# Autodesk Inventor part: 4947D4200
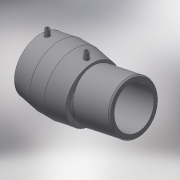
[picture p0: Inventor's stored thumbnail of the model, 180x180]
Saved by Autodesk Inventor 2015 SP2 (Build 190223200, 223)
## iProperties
Created: 2017-06
Part Number: 4947D4200
Material: Generic
Description: PLASSON ADJUSTABLE ELBOW (ONE SIDE) 200
Document SubType Name: Modeling
Designer: KIM
Mass: 55.0731 g
Surface Area: 148.067 cm^2
Volume: 55.0731 cm^3
Density: 1 g/cm^3
Appearance: Default
Author: KIM
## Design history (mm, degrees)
derived "4947D4.ipt"
feature "Solid1::4947D4.ipt"
tag "TaggingFeature1"
body "Solid1"
other parameters: "d0" = 194.25, "d3" = 104, "d4" = 52, "d5" = 225, "d8" = 168 deg, "d10" = 41.6, "d11" = 13.86667, "d29" = 125, "d30" = 15, "d31" = 74, "d34" = 5 deg, "d41" = 4, "d42" = 14, "d43" = 0, "d55" = 54.15, "d57" = 168 deg, "d62" = 3, "d63" = 0, "d68" = 135 deg, "d69" = 116, "d70" = 92.5, "d71" = 5, "L_1" = 104, "A_" = 125, "d_2" = 12, "L_0" = 148, "L_2" = 116, "d54" = 90.25, "d59" = 230.09945
